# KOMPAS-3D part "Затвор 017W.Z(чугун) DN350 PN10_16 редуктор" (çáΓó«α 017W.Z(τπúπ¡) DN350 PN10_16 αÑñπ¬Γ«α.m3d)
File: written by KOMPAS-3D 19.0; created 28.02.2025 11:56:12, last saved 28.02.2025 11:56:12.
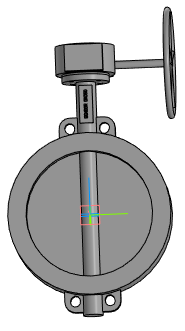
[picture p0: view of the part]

Document properties: Автор: Евгений; Полное имя файла: Затвор 017W.Z(чугун) DN350 PN10_16 редуктор.a3d

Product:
- Part/product: Затвор 017W.Z(чугун) DN350 PN10_16 редуктор
    Масса: 74.7824

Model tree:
1. Операция без истории:1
